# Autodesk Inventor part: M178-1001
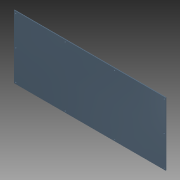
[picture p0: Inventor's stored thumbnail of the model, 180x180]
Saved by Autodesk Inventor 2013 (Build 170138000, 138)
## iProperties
Created: 2004-11
Part Number: M178-1001
Document SubType Name: Modeling
Designer: Autodesk, Inc.
Manufacturer: Standard
Standards Organization: Custom
Material: Allgemein
Description: TABLE TOP, WORKSTATION
Mass: 13264.3 g
Surface Area: 28374 cm^2
Volume: 13264.3 cm^3
Density: 1 g/cm^3
CAGE: 1LJX3
Dept. ID: Product Design
Description #2: ---
Finish #1: ---
Finish #2: ---
Material ID: ---
Project Number: ---
Author: Autodesk, Inc.
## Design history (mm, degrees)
sketch "Sketch1"
  geometry: L1 (-914.4, 381)-(914.4, 381); L2 (914.4, 381)-(914.4, -381); L3 (914.4, -381)-(-914.4, -381); L4 (-914.4, -381)-(-914.4, 381); 3 further points
  constraints: 8 end point, 2 midpoint, 2 parallel, 1 horizontal, 1 horizontal alignment, 1 perpendicular, 1 vertical alignment, 1 other
  dimensions: "d0" = 1828.8 distance of L1.start L1.end; "d1" = 762 distance of L3.end L1.start
extrude "Extrusion1" new body sketch "Sketch1" distance "d2" = 9.525; taper "d3" = 0 deg
sketch "Sketch2"
  geometry: L1 (-914.4, -381)-(-914.4, 381) reference; L2 (914.4, -381)-(-914.4, -381) reference; 1 further point
  dimensions: "d4" = 20 distance from line of L1 point (-894.4, -361); "d5" = 20 distance from line of point (-894.4, -361) L2
hole "Hole1" sketch "Sketch2" diameter "d6" = 8.9916; stored, may be unused: countersink angle "d10" = 90 deg, drill point angle "d12" = 118 deg; dims "d7" = 12.7, "d8" = 17.2974, "d9" = 6.35, "d11" = 19.05
pattern_linear "Rectangular Pattern1" dims "d15" = 722 (computed from d1), "d18" = 1788.8 (computed from d0)
body "Solid1"
